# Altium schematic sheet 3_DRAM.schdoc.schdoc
size 426 x 302 mm; Symbol: Sheet_A3_Whycan; Device: Sheet_A3; @Project Name: Avaota Pi A; REV: 1.0; Company: YuzukiHD; Draw By: GloomyGhost; @Update Date: 2024-02-20; @Page No: 5; @Page Count: 12
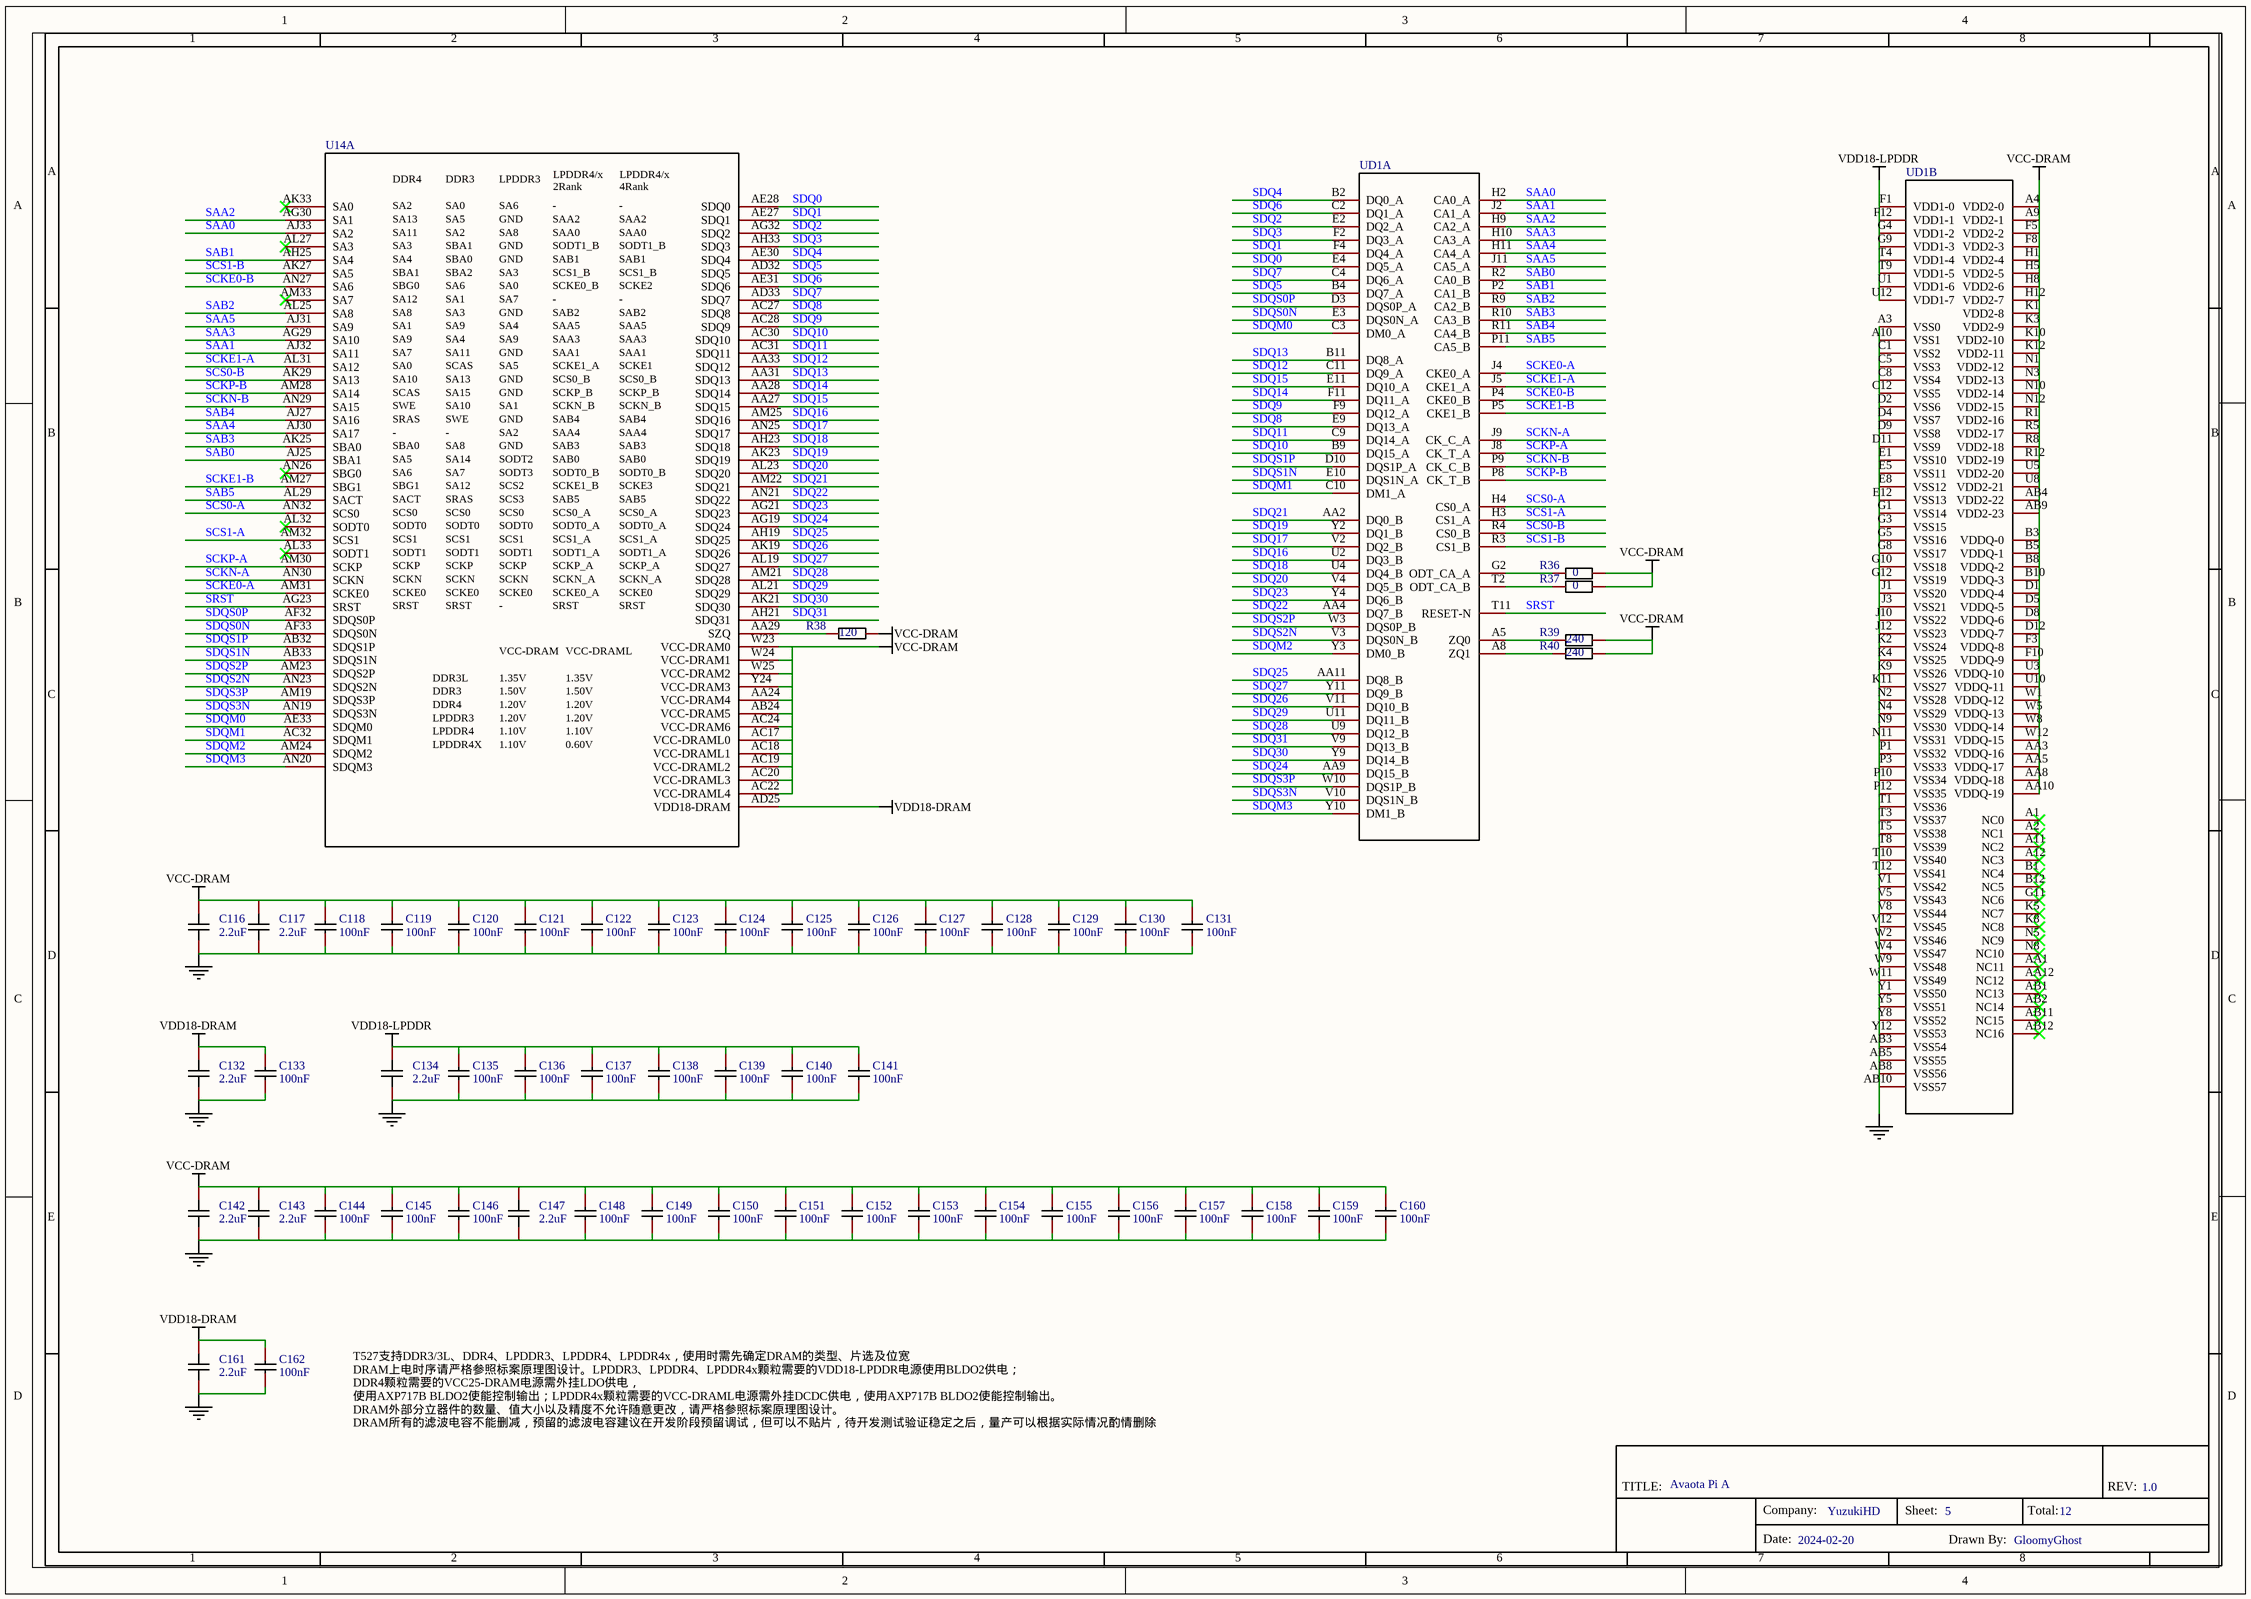
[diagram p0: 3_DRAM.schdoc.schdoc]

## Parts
C116  2.2uF  [c0201 nsk]
C117  2.2uF  [c0201 nsk]
C118  100nF  [c0201 nsk]
C119  100nF  [c0201 nsk]
C120  100nF  [c0201 nsk]
C121  100nF  [c0201 nsk]
C122  100nF  [c0201 nsk]
C123  100nF  [c0201 nsk]
C124  100nF  [c0201 nsk]
C125  100nF  [c0201 nsk]
C126  100nF  [c0201 nsk]
C127  100nF  [c0201 nsk]
C128  100nF  [c0201 nsk]
C129  100nF  [c0201 nsk]
C130  100nF  [c0201 nsk]
C131  100nF  [c0201 nsk]
C132  2.2uF  [c0201 nsk]
C133  100nF  [c0201 nsk]
C134  2.2uF  [c0201 nsk]
C135  100nF  [c0201 nsk]
C136  100nF  [c0201 nsk]
C137  100nF  [c0201 nsk]
C138  100nF  [c0201 nsk]
C139  100nF  [c0201 nsk]
C140  100nF  [c0201 nsk]
C141  100nF  [c0201 nsk]
C142  2.2uF  [c0201 nsk]
C143  2.2uF  [c0201 nsk]
C144  100nF  [c0201 nsk]
C145  100nF  [c0201 nsk]
C146  100nF  [c0201 nsk]
C147  2.2uF  [c0201 nsk]
C148  100nF  [c0201 nsk]
C149  100nF  [c0201 nsk]
C150  100nF  [c0201 nsk]
C151  100nF  [c0201 nsk]
C152  100nF  [c0201 nsk]
C153  100nF  [c0201 nsk]
C154  100nF  [c0201 nsk]
C155  100nF  [c0201 nsk]
C156  100nF  [c0201 nsk]
C157  100nF  [c0201 nsk]
C158  100nF  [c0201 nsk]
C159  100nF  [c0201 nsk]
C160  100nF  [c0201 nsk]
C161  2.2uF  [c0201 nsk]
C162  100nF  [c0201 nsk]
R36  0  [r0201 nsk]
R37  0  [r0201 nsk]
R38  120  [r0201 nsk]
R39  240  [r0201 nsk]
R40  240  [r0201 nsk]
U14  T527  [T527-BGA664]  (value not drawn)  (part A of 8)
UD1  LPDDR4_FBGA200  [BGA200P65_80B1000_1500H90]  (value not drawn)  (parts A,B of 2)

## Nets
NetC116_2: C116.2 C117.2 C118.1 C119.1 C120.1 C121.1 C122.1 C123.1 C124.1 C125.1 C126.1 C127.1 C128.1 C129.1 C130.1 C131.1 C132.2 C133.1 C134.2 C135.1 C136.1 C137.1 C138.1 C139.1 C140.1 C141.1 C142.2 C143.2 C144.1 C145.1 C146.1 C147.2 C148.1 C149.1 C150.1 C151.1 C152.1 C153.1 C154.1 C155.1 C156.1 C157.1 C158.1 C159.1 C160.1 C161.2 C162.1 UD1.A3(VSS0) UD1.A10(VSS1) UD1.AB3(VSS54) UD1.AB5(VSS55) UD1.AB8(VSS56) UD1.AB10(VSS57) UD1.C1(VSS2) UD1.C5(VSS3) UD1.C8(VSS4) UD1.C12(VSS5) UD1.D2(VSS6) UD1.D4(VSS7) UD1.D9(VSS8) UD1.D11(VSS9) UD1.E1(VSS10) UD1.E5(VSS11) UD1.E8(VSS12) UD1.E12(VSS13) UD1.G1(VSS14) UD1.G3(VSS15) UD1.G5(VSS16) UD1.G8(VSS17) UD1.G10(VSS18) UD1.G12(VSS19) UD1.J1(VSS20) UD1.J3(VSS21) UD1.J10(VSS22) UD1.J12(VSS23) UD1.K2(VSS24) UD1.K4(VSS25) UD1.K9(VSS26) UD1.K11(VSS27) UD1.N2(VSS28) UD1.N4(VSS29) UD1.N9(VSS30) UD1.N11(VSS31) UD1.P1(VSS32) UD1.P3(VSS33) UD1.P10(VSS34) UD1.P12(VSS35) UD1.T1(VSS36) UD1.T3(VSS37) UD1.T5(VSS38) UD1.T8(VSS39) UD1.T10(VSS40) UD1.T12(VSS41) UD1.V1(VSS42) UD1.V5(VSS43) UD1.V8(VSS44) UD1.V12(VSS45) UD1.W2(VSS46) UD1.W4(VSS47) UD1.W9(VSS48) UD1.W11(VSS49) UD1.Y1(VSS50) UD1.Y5(VSS51) UD1.Y8(VSS52) UD1.Y12(VSS53)
VCC-DRAM: C116.1 C117.1 C118.2 C119.2 C120.2 C121.2 C122.2 C123.2 C124.2 C125.2 C126.2 C127.2 C128.2 C129.2 C130.2 C131.2 C142.1 C143.1 C144.2 C145.2 C146.2 C147.1 C148.2 C149.2 C150.2 C151.2 C152.2 C153.2 C154.2 C155.2 C156.2 C157.2 C158.2 C159.2 C160.2 R36.2 R37.2 R38.2 R39.2 R40.2 U14.AA24(VCC-DRAM4) U14.AB24(VCC-DRAM5) U14.AC17(VCC-DRAML0) U14.AC18(VCC-DRAML1) U14.AC19(VCC-DRAML2) U14.AC20(VCC-DRAML3) U14.AC22(VCC-DRAML4) U14.AC24(VCC-DRAM6) U14.W23(VCC-DRAM0) U14.W24(VCC-DRAM1) U14.W25(VCC-DRAM2) U14.Y24(VCC-DRAM3) UD1.A4(VDD2-0) UD1.A9(VDD2-1) UD1.AA3(VDDQ-16) UD1.AA5(VDDQ-17) UD1.AA8(VDDQ-18) UD1.AA10(VDDQ-19) UD1.AB4(VDD2-22) UD1.AB9(VDD2-23) UD1.B3(VDDQ-0) UD1.B5(VDDQ-1) UD1.B8(VDDQ-2) UD1.B10(VDDQ-3) UD1.D1(VDDQ-4) UD1.D5(VDDQ-5) UD1.D8(VDDQ-6) UD1.D12(VDDQ-7) UD1.F3(VDDQ-8) UD1.F5(VDD2-2) UD1.F8(VDD2-3) UD1.F10(VDDQ-9) UD1.H1(VDD2-4) UD1.H5(VDD2-5) UD1.H8(VDD2-6) UD1.H12(VDD2-7) UD1.K1(VDD2-8) UD1.K3(VDD2-9) UD1.K10(VDD2-10) UD1.K12(VDD2-11) UD1.N1(VDD2-12) UD1.N3(VDD2-13) UD1.N10(VDD2-14) UD1.N12(VDD2-15) UD1.R1(VDD2-16) UD1.R5(VDD2-17) UD1.R8(VDD2-18) UD1.R12(VDD2-19) UD1.U3(VDDQ-10) UD1.U5(VDD2-20) UD1.U8(VDD2-21) UD1.U10(VDDQ-11) UD1.W1(VDDQ-12) UD1.W5(VDDQ-13) UD1.W8(VDDQ-14) UD1.W12(VDDQ-15)
VDD18-DRAM: C132.1 C133.2 C161.1 C162.2 U14.AD25(VDD18-DRAM)
VDD18-LPDDR: C134.1 C135.2 C136.2 C137.2 C138.2 C139.2 C140.2 C141.2 UD1.F1(VDD1-0) UD1.F12(VDD1-1) UD1.G4(VDD1-2) UD1.G9(VDD1-3) UD1.T4(VDD1-4) UD1.T9(VDD1-5) UD1.U1(VDD1-6) UD1.U12(VDD1-7)
SAA0: U14.AJ33(SA2) UD1.H2(CA0_A)
SAA1: U14.AJ32(SA11) UD1.J2(CA1_A)
SAA2: U14.AG30(SA1) UD1.H9(CA2_A)
SAA3: U14.AG29(SA10) UD1.H10(CA3_A)
SAA4: U14.AJ30(SA17) UD1.H11(CA4_A)
SAA5: U14.AJ31(SA9) UD1.J11(CA5_A)
SAB0: U14.AJ25(SBA1) UD1.R2(CA0_B)
SAB1: U14.AH25(SA4) UD1.P2(CA1_B)
SAB2: U14.AL25(SA8) UD1.R9(CA2_B)
SAB3: U14.AK25(SBA0) UD1.R10(CA3_B)
SAB4: U14.AJ27(SA16) UD1.R11(CA4_B)
SAB5: U14.AL29(SACT) UD1.P11(CA5_B)
SCKE0-A: U14.AM31(SCKE0) UD1.J4(CKE0_A)
SCKE0-B: U14.AN27(SA6) UD1.P4(CKE0_B)
SCKE1-A: U14.AL31(SA12) UD1.J5(CKE1_A)
SCKE1-B: U14.AM27(SBG1) UD1.P5(CKE1_B)
SCKN-A: U14.AN30(SCKN) UD1.J9(CK_C_A)
SCKN-B: U14.AN29(SA15) UD1.P9(CK_C_B)
SCKP-A: U14.AM30(SCKP) UD1.J8(CK_T_A)
SCKP-B: U14.AM28(SA14) UD1.P8(CK_T_B)
SCS0-A: U14.AN32(SCS0) UD1.H4(CS0_A)
SCS0-B: U14.AK29(SA13) UD1.R4(CS0_B)
SCS1-A: U14.AM32(SCS1) UD1.H3(CS1_A)
SCS1-B: U14.AK27(SA5) UD1.R3(CS1_B)
SDQ0: U14.AE28(SDQ0) UD1.E4(DQ5_A)
SDQ1: U14.AE27(SDQ1) UD1.F4(DQ4_A)
SDQ2: U14.AG32(SDQ2) UD1.E2(DQ2_A)
SDQ3: U14.AH33(SDQ3) UD1.F2(DQ3_A)
SDQ4: U14.AE30(SDQ4) UD1.B2(DQ0_A)
SDQ5: U14.AD32(SDQ5) UD1.B4(DQ7_A)
SDQ6: U14.AE31(SDQ6) UD1.C2(DQ1_A)
SDQ7: U14.AD33(SDQ7) UD1.C4(DQ6_A)
SDQ8: U14.AC27(SDQ8) UD1.E9(DQ13_A)
SDQ9: U14.AC28(SDQ9) UD1.F9(DQ12_A)
SDQ10: U14.AC30(SDQ10) UD1.B9(DQ15_A)
SDQ11: U14.AC31(SDQ11) UD1.C9(DQ14_A)
SDQ12: U14.AA33(SDQ12) UD1.C11(DQ9_A)
SDQ13: U14.AA31(SDQ13) UD1.B11(DQ8_A)
SDQ14: U14.AA28(SDQ14) UD1.F11(DQ11_A)
SDQ15: U14.AA27(SDQ15) UD1.E11(DQ10_A)
SDQ16: U14.AM25(SDQ16) UD1.U2(DQ3_B)
SDQ17: U14.AN25(SDQ17) UD1.V2(DQ2_B)
SDQ18: U14.AH23(SDQ18) UD1.U4(DQ4_B)
SDQ19: U14.AK23(SDQ19) UD1.Y2(DQ1_B)
SDQ20: U14.AL23(SDQ20) UD1.V4(DQ5_B)
SDQ21: U14.AM22(SDQ21) UD1.AA2(DQ0_B)
SDQ22: U14.AN21(SDQ22) UD1.AA4(DQ7_B)
SDQ23: U14.AG21(SDQ23) UD1.Y4(DQ6_B)
SDQ24: U14.AG19(SDQ24) UD1.AA9(DQ15_B)
SDQ25: U14.AH19(SDQ25) UD1.AA11(DQ8_B)
SDQ26: U14.AK19(SDQ26) UD1.V11(DQ10_B)
SDQ27: U14.AL19(SDQ27) UD1.Y11(DQ9_B)
SDQ28: U14.AM21(SDQ28) UD1.U9(DQ12_B)
SDQ29: U14.AL21(SDQ29) UD1.U11(DQ11_B)
SDQ30: U14.AK21(SDQ30) UD1.Y9(DQ14_B)
SDQ31: U14.AH21(SDQ31) UD1.V9(DQ13_B)
SDQM0: U14.AE33(SDQM0) UD1.C3(DM0_A)
SDQM1: U14.AC32(SDQM1) UD1.C10(DM1_A)
SDQM2: U14.AM24(SDQM2) UD1.Y3(DM0_B)
SDQM3: U14.AN20(SDQM3) UD1.Y10(DM1_B)
SDQS0N: U14.AF33(SDQS0N) UD1.E3(DQS0N_A)
SDQS0P: U14.AF32(SDQS0P) UD1.D3(DQS0P_A)
SDQS1N: U14.AB33(SDQS1N) UD1.E10(DQS1N_A)
SDQS1P: U14.AB32(SDQS1P) UD1.D10(DQS1P_A)
SDQS2N: U14.AN23(SDQS2N) UD1.V3(DQS0N_B)
SDQS2P: U14.AM23(SDQS2P) UD1.W3(DQS0P_B)
SDQS3N: U14.AN19(SDQS3N) UD1.V10(DQS1N_B)
SDQS3P: U14.AM19(SDQS3P) UD1.W10(DQS1P_B)
SRST: U14.AG23(SRST) UD1.T11(RESET-N)
NetR36_1: R36.1 UD1.G2(ODT_CA_A)
NetR37_1: R37.1 UD1.T2(ODT_CA_B)
NetR38_1: R38.1 U14.AA29(SZQ)
NetR39_1: R39.1 UD1.A5(ZQ0)
NetR40_1: R40.1 UD1.A8(ZQ1)

Not connected (* = marked no-connect by the designer): U14 AK33(SA0)* AL27(SA3)* AL32(SODT0)* AL33(SODT1)* AM33(SA7)* AN26(SBG0)*; UD1 A1(NC0)* A2(NC1)* A11(NC2)* A12(NC3)* AA1(NC11)* AA12(NC12)* AB1(NC13)* AB2(NC14)* AB11(NC15)* AB12(NC16)* B1(NC4)* B12(NC5)* G11(NC6)* K5(NC7)* K8(NC8)* N5(NC9)* N8(NC10)*

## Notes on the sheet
- T527支持DDR3/3L、DDR4、LPDDR3、LPDDR4、LPDDR4x，使用时需先确定DRAM的类型、片选及位宽
  DRAM上电时序请严格参照标案原理图设计。LPDDR3、LPDDR4、LPDDR4x颗粒需要的VDD18-LPDDR电源使用BLDO2供电；
  DDR4颗粒需要的VCC25-DRAM电源需外挂LDO供电，
  使用AXP717B BLDO2使能控制输出；LPDDR4x颗粒需要的VCC-DRAML电源需外挂DCDC供电，使用AXP717B BLDO2使能控制输出。
  DRAM外部分立器件的数量、值大小以及精度不允许随意更改，请严格参照标案原理图设计。
  DRAM所有的滤波电容不能删减，预留的滤波电容建议在开发阶段预留调试，但可以不贴片，待开发测试验证稳定之后，量产可以根据实际情况酌情删除

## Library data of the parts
C116 C117 C132 C134 C142 C143 C147 C161 = 0201X225M6R3NT: Manufacturer: FH(风华); Add into BOM: yes; Tolerance: ±20%; Voltage Rated: 6.3V; Temperature Coefficient: X5R; Description: 容值:2.2uF;精度:±20%;额定电压:6.3V;材质(温度系数):X5R;
C118-C131 C133 C135-C141 C144-C146 C148-C160 C162 = GRM033R61A104KE15D: Manufacturer: muRata(村田); Add into BOM: yes; Tolerance: ±10%; Voltage Rated: 10V; Temperature Coefficient: X5R; Description: 容值:100nF;精度:±10%;额定电压:10V;材质(温度系数):X5R;
R36-R40 = Res_0201: Symbol: 电阻; Convert to PCB: yes
U14 = T527: Add into BOM: yes; SWAP_INFO: (S1+S2+S3+S4+S5+S6+S7+S8+S9); SPLIT_INST: TRUE; Description: Allwinner T527 SoC
UD1 = LPDDR4_FBGA200: Add into BOM: yes; SWAP_INFO: (S1+S2); SPLIT_INST: TRUE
